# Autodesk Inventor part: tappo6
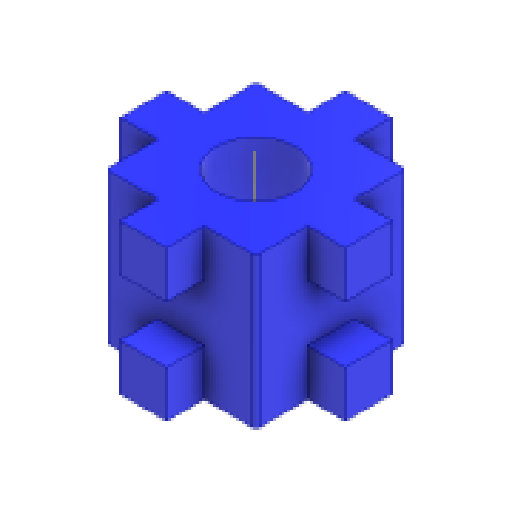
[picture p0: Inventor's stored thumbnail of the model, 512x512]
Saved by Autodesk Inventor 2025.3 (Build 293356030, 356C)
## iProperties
Created: 2026-03
Part Number: tappo6
Material: Generico
Document SubType Name: Modeling
Designer: R5800u
Density: 1 g/cm^3
Appearance: Blu - Pittura muro - Lucida
Author: R5800u
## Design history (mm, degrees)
sketch "Schizzo1"
  geometry: L1 (10, 10)-(-10, 10); L2 (-10, 10)-(-10, -10); L3 (-10, -10)-(10, -10); L4 (10, -10)-(10, 10); L5 (10, 10)-(-10, -10); L6 (-10, 10)-(10, -10); L7 (3, -8)-(3, -9.7) reference; L8 (-3, -9.7)-(-3, -8) reference; L9 (3.1, 10)-(-3.1, 10); L10 (-3.1, 10)-(-3.1, -10); L11 (-3.1, -10)-(3.1, -10); L12 (3.1, -10)-(3.1, 10); L13 (3.1, 10)-(-3.1, -10); L14 (-3.1, 10)-(3.1, -10); L15 (3.1, 3.8)-(-3.1, 3.8); 3 further points
  constraints: 26 end point, 4 midpoint, 4 parallel, 3 perpendicular, 3 point on line, 2 horizontal
  dimensions: "d0" = 20 distance of L3.end L2.end; "d1" = 20 distance of L2.end L1.end; "d2" = 6.2 distance of L11.end L10.end; "d3" = 6.2 distance between parallel lines of L9 L15
  node "Riferimento1"
  node "Riferimento2"
extrude "Estrusione1" new body sketch "Schizzo1" distance "d4" = 10; taper "d5" = 0 deg
extrude "Estrusione2" join sketch "Schizzo1" distance "d6" = 5; taper "d7" = 0 deg
mirror "Speculare1"
node "Asse di lavoro1"
pattern_circular "Serie circolare1" dims "d9" = 360 deg
fillet "Raccordo1" dims "d11" = 0.5
sketch "Schizzo2"
  geometry: L1 (0, -5)-(6.2, -5) reference; L2 (6.2, -25)-(0, -25) reference; L3 (3.1, -5)-(3.1, -25); 1 further point
  constraints: 2 end point, 2 midpoint
hole "Foro1" sketch "Schizzo2" at (3.1, -15) diameter "d12" = 10.5; stored, may be unused: countersink angle "d16" = 90 deg, drill point angle "d18" = 118 deg; dims "d13" = 6, "d14" = 8, "d15" = 4.6, "d17" = 8
node "Solido1"
